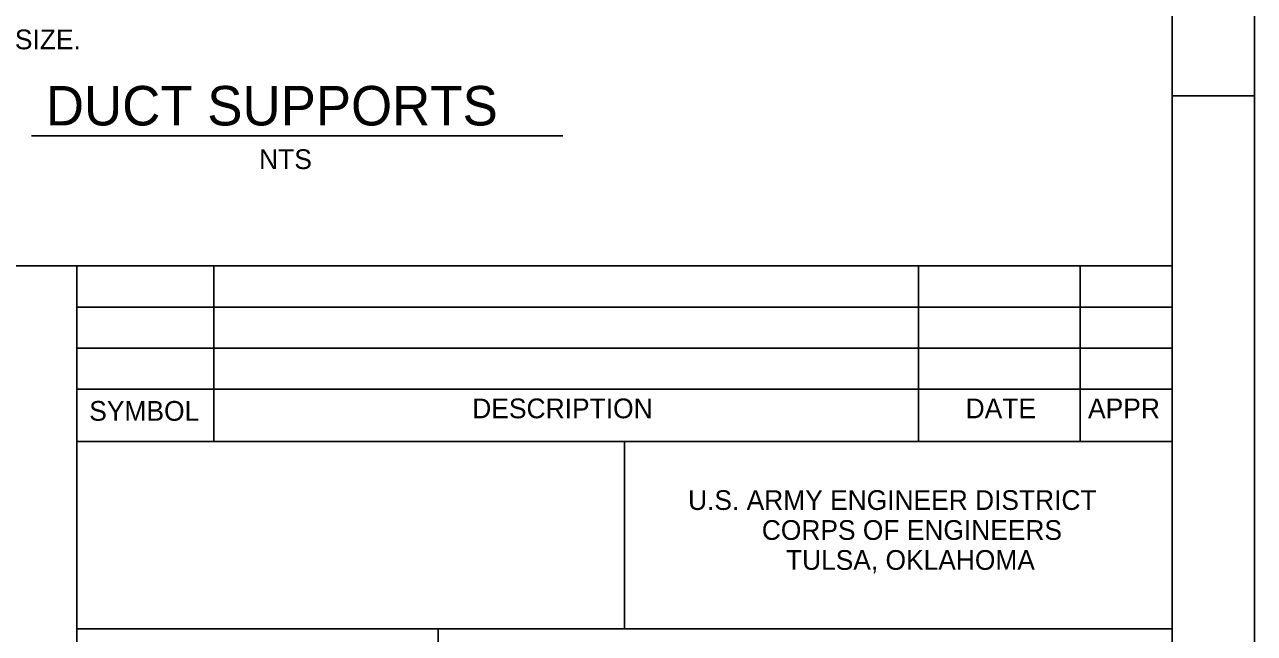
# Model space of a CAD drawing. Extents: x 10040.55 to 10045.84, y 10033.26 to 10035.76.
# Drawn here: x 10043.424 to 10044.047, y 10033.629 to 10033.937 of the extents above; entities that cross this region are included whole.
import ezdxf

# ---------------------------------------------------------------- set-up
doc = ezdxf.new("R2010")
doc.units = 0
doc.layers.add('Level 1', color=7, linetype='Continuous')
doc.layers.add('Level 2', color=7, linetype='Continuous')

msp = doc.modelspace()

# ---------------------------------------------------------------- linework, layer by layer
at = {"layer": 'Level 1'}
for p, q in [((10044.04697, 10035.75552), (10044.04697, 10033.25552)), ((10044.0053, 10035.71385), (10044.0053, 10033.29719)), ((10044.04697, 10033.90105), (10044.00561, 10033.90105)), ((10043.45065, 10033.8149), (10043.45065, 10033.72594)), ((10044.0053, 10033.8149), (10043.45065, 10033.8149)), ((10043.51997, 10033.8149), (10043.51997, 10033.72635)), ((10043.8768, 10033.8149), (10043.8768, 10033.72635)), ((10043.95872, 10033.8149), (10043.95872, 10033.72635)), ((10044.0053, 10033.79406), (10043.45065, 10033.79406)), ((10043.45065, 10033.77323), (10044.0053, 10033.77323)), ((10043.45065, 10033.7524), (10044.0053, 10033.7524)), ((10043.45065, 10033.29926), (10043.45065, 10033.72594)), ((10044.0053, 10033.72594), (10043.45065, 10033.72594)), ((10043.72797, 10033.6311), (10043.72797, 10033.72594)), ((10043.45065, 10033.6311), (10044.0053, 10033.6311)), ((10043.63372, 10033.6311), (10043.63372, 10033.36549))]:
    msp.add_line(p, q, dxfattribs=at)
at = {"layer": 'Level 2'}
for p, q in [((10043.42775, 10033.88075), (10043.69677, 10033.88075)), ((10043.13379, 10033.8149), (10043.45065, 10033.8149))]:
    msp.add_line(p, q, dxfattribs=at)

# ---------------------------------------------------------------- texts
at = {"layer": 'Level 1'}
for s, height, p in [('DESCRIPTION', 0.01, (10043.65089, 10033.73773)), ('DATE', 0.01, (10043.90072, 10033.73773)), ('APPR', 0.01, (10043.96272, 10033.73773)), ('SYMBOL', 0.01, (10043.45694, 10033.73646)), ('U.S. ARMY ENGINEER DISTRICT', 0.0099792, (10043.76018, 10033.69131)), ('CORPS OF ENGINEERS', 0.0099792, (10043.79753, 10033.67615)), ('TULSA, OKLAHOMA', 0.0099792, (10043.80975, 10033.66098))]:
    msp.add_text(s, height=height, dxfattribs=at).set_placement(p)
at = {"layer": 'Level 2'}
for s, height, p in [('   AND GREATER DUCT SIZE.', 0.01, (10043.26697, 10033.92458)), ('DUCT SUPPORTS', 0.02, (10043.435, 10033.88601)), ('NTS', 0.01, (10043.54296, 10033.86394))]:
    msp.add_text(s, height=height, dxfattribs=at).set_placement(p)

doc.saveas('drawing.dxf')
